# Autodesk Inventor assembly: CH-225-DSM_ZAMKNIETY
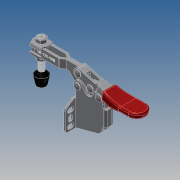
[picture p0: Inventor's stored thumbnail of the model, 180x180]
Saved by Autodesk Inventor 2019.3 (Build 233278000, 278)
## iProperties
Company: ·L?¤¤?
Created: 2010-06
Part Number: CH-225-DSM_ZAMKNIETY
Material: Ogólny
Description: STEP AP203
Document SubType Name: Assembly
Designer: CADENGINEERING4
Sending System: SolidWorks 2005179
Preprocessor: SwSTEP 2.0
Title: CH-225-DSM.STEP
Author: ·L?¥Î?
Revision Number: ANY
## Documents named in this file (9)
- E:\STRONA\Horizontal toggle clamp\CH-225-DSM\CH-225-DSM_ZAMKNIETY.iam
- E:\STRONA\Horizontal toggle clamp\CH-225-DSM\CH-FC-56212___.ipt
- E:\STRONA\Horizontal toggle clamp\CH-225-DSM\225-DSM-02___.ipt
- E:\STRONA\Horizontal toggle clamp\CH-225-DSM\225-D-04___.ipt
- E:\STRONA\Horizontal toggle clamp\CH-225-DSM\FW-516___.ipt
- E:\STRONA\Horizontal toggle clamp\CH-225-DSM\225-D-05___.ipt
- E:\STRONA\Horizontal toggle clamp\CH-225-DSM\56212-01___.ipt
- E:\STRONA\Horizontal toggle clamp\CH-225-DSM\225-D-03___.iam
- E:\STRONA\Horizontal toggle clamp\CH-225-DSM\225-DSM-01___.ipt
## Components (14 placed, 14 different names)
1. CH-FC-56212_??_1 — Równoległe:3, Zestawiające:1, Zestawiające:2, Zestawiające:4, Zestawiające:5, Zestawiające:9
2. 225-DSM-02_??_2 — Równoległe:1, Zestawiające:7, Zestawiające:8, Zestawiające:9, Zestawiające:21, Zestawiające:22, Zestawiające:25
3. 225-D-04_??_3 — Zestawiające:10, Zestawiające:11, Zestawiające:12
4. FW-516_??_4 — Równoległe:2, Zestawiające:4, Zestawiające:6, Zestawiające:7
5. 225-D-05_??_5 — Zestawiające:22, Zestawiające:26
6. 56212-01_??_6 — Zestawiające:5, Zestawiające:6
7. 225-D-03_??_7 [sub-assembly] — Zestawiające:17, Zestawiające:18, Zestawiające:19, Zestawiające:20, Zestawiające:23, Zestawiające:24, Przejściowe:1
8. 225-D-04_??_8 — Zestawiające:10, Zestawiające:11, Zestawiające:12, Zestawiające:13, Zestawiające:14, Zestawiające:17, Zestawiające:18
9. 225-D-05_??_9 — Zestawiające:19, Zestawiające:20
10. 225-DSM-01_??_10 — Zestawiające:13, Zestawiające:14, Zestawiające:15, Zestawiające:16, Zestawiające:21, Zestawiające:26, Przejściowe:1
11. FW-516_??_11 — Równoległe:1, Równoległe:2, Zestawiające:2, Zestawiające:3, Zestawiające:8
12. 225-D-05_??_12 — Zestawiające:23, Zestawiające:24, Zestawiające:25
13. 225-D-05_??_13 — Zestawiające:15, Zestawiające:16
14. 56212-01_??_15 — Równoległe:3, Zestawiające:1, Zestawiające:3
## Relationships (30: Mate 26, Flush 3, Transitional 1)
- Równoległe:1 [Flush]: 225-DSM-02_??_2 ↔ FW-516_??_11
- Równoległe:2 [Flush]: FW-516_??_4 ↔ FW-516_??_11
- Równoległe:3 [Flush]: CH-FC-56212_??_1 ↔ 56212-01_??_15
- Zestawiające:1 [Mate]: CH-FC-56212_??_1 ↔ 56212-01_??_15
- Zestawiające:2 [Mate]: CH-FC-56212_??_1 ↔ FW-516_??_11
- Zestawiające:3 [Mate]: FW-516_??_11 ↔ 56212-01_??_15
- Zestawiające:4 [Mate]: CH-FC-56212_??_1 ↔ FW-516_??_4
- Zestawiające:5 [Mate]: CH-FC-56212_??_1 ↔ 56212-01_??_6
- Zestawiające:6 [Mate]: FW-516_??_4 ↔ 56212-01_??_6
- Zestawiające:7 [Mate]: 225-DSM-02_??_2 ↔ FW-516_??_4
- Zestawiające:8 [Mate]: 225-DSM-02_??_2 ↔ FW-516_??_11
- Zestawiające:9 [Mate]: CH-FC-56212_??_1 ↔ 225-DSM-02_??_2
- Zestawiające:10 [Mate]: 225-D-04_??_3 ↔ 225-D-04_??_8
- Zestawiające:11 [Mate]: 225-D-04_??_3 ↔ 225-D-04_??_8
- Zestawiające:12 [Mate]: 225-D-04_??_3 ↔ 225-D-04_??_8
- Zestawiające:13 [Mate]: 225-D-04_??_8 ↔ 225-DSM-01_??_10
- Zestawiające:14 [Mate]: 225-D-04_??_8 ↔ 225-DSM-01_??_10
- Zestawiające:15 [Mate]: 225-DSM-01_??_10 ↔ 225-D-05_??_13
- Zestawiające:16 [Mate]: 225-DSM-01_??_10 ↔ 225-D-05_??_13
- Zestawiające:17 [Mate]: 225-D-03_??_7 ↔ 225-D-04_??_8
- Zestawiające:18 [Mate]: 225-D-03_??_7 ↔ 225-D-04_??_8
- Zestawiające:19 [Mate]: 225-D-03_??_7 ↔ 225-D-05_??_9
- Zestawiające:20 [Mate]: 225-D-03_??_7 ↔ 225-D-05_??_9
- Zestawiające:21 [Mate]: 225-DSM-02_??_2 ↔ 225-DSM-01_??_10
- Zestawiające:22 [Mate]: 225-DSM-02_??_2 ↔ 225-D-05_??_5
- Zestawiające:23 [Mate]: 225-D-03_??_7 ↔ 225-D-05_??_12
- Zestawiające:24 [Mate]: 225-D-03_??_7 ↔ 225-D-05_??_12
- Zestawiające:25 [Mate]: 225-DSM-02_??_2 ↔ 225-D-05_??_12
- Zestawiające:26 [Mate]: 225-D-05_??_5 ↔ 225-DSM-01_??_10
- Przejściowe:1 [Transitional]: 225-D-03_??_7 ↔ 225-DSM-01_??_10
